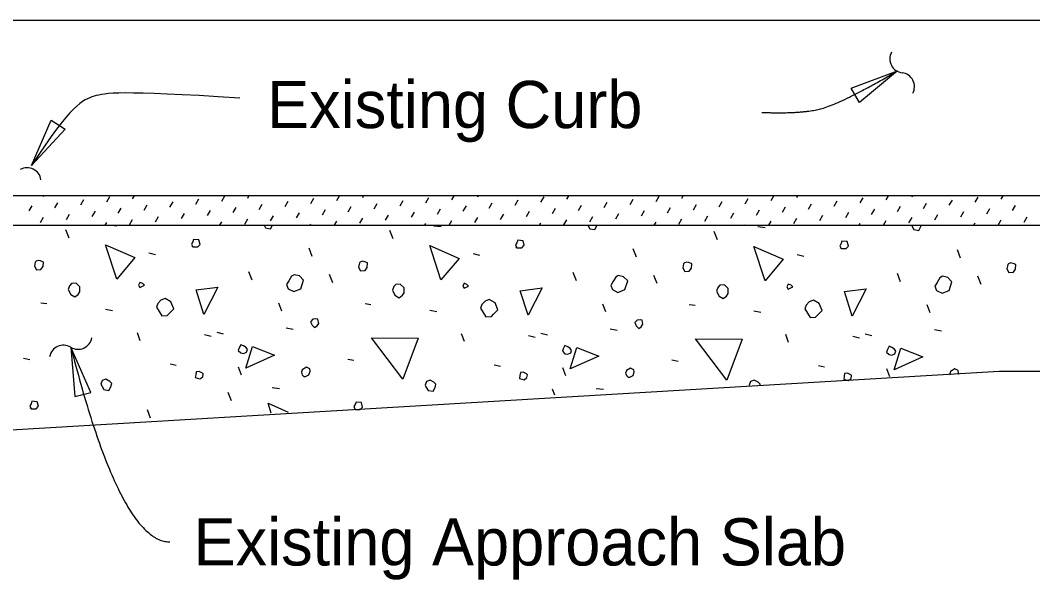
# Model space of a CAD drawing. Extents: x 21587 to 21659.1, y 56113.9 to 56155.9.
# Drawn here: x 21594.998 to 21599.323, y 56132.413 to 56134.801 of the extents above; entities that cross this region are included whole.
import ezdxf

# ---------------------------------------------------------------- set-up
doc = ezdxf.new("R2010")
doc.units = 0
for name, color, linetype in [('AdhocPoint_dp', 7, 'Continuous'), ('PlotBorder_dp', 7, 'Continuous'), ('SheetBorder_dp', 7, 'Continuous'), ('TextMisc', 7, 'Continuous')]:
    doc.layers.add(name, color=color, linetype=linetype)

msp = doc.modelspace()

# ---------------------------------------------------------------- linework, layer by layer
at = {"layer": 'AdhocPoint_dp'}
for p, q in [((21593.9596, 56134.8009), (21601.9067, 56134.8009)), ((21604.323, 56134.0511), (21593.9596, 56134.0511)), ((21593.9596, 56133.926), (21604.323, 56133.926)), ((21599.1795, 56133.301), (21594.9596, 56133.051)), ((21604.323, 56133.301), (21599.1795, 56133.301))]:
    msp.add_line(p, q, dxfattribs=at)
at = {"layer": 'PlotBorder_dp'}
for points in [[(21598.7452, 56134.5845), (21598.5825, 56134.4497), (21598.5472, 56134.5108)], [(21595.0458, 56134.1809), (21595.13, 56134.3747), (21595.1891, 56134.3361)], [(21595.2137, 56133.4055), (21595.2308, 56133.1949), (21595.2992, 56133.2123)]]:
    msp.add_lwpolyline(points, close=True, dxfattribs=at)
for centre, start, end in [((21598.7718, 56134.636), 151.5267, 263.2539), ((21598.7578, 56134.5176), 331.5267, 83.2539), ((21595.0274, 56134.1118), 7.9536, 119.6808), ((21595.2447, 56133.456), 238.4384, 350.1656), ((21595.1822, 56133.3544), 58.4384, 170.1656)]:
    msp.add_arc(centre, 0.0596, start, end, dxfattribs=at)
for points, degree in [([(21598.1653, 56134.4076), (21598.3174, 56134.4019), (21598.4885, 56134.4362), (21598.7452, 56134.5845)], 2), ([(21595.9359, 56134.4685), (21595.4144, 56134.5022), (21595.311, 56134.48), (21595.217, 56134.4435), (21595.0459, 56134.181)], 3), ([(21595.2142, 56133.4054), (21595.4254, 56132.5742), (21595.6366, 56132.5742)], 2)]:
    msp.add_open_spline(points, degree=degree, dxfattribs=at)
at = {"layer": 'TextMisc'}
for p, q in [((21595.0973, 56134.0487), (21595.0987, 56134.0511)), ((21595.3674, 56134.0258), (21595.3804, 56134.0482)), ((21595.478, 56134.0388), (21595.4852, 56134.0511)), ((21595.8588, 56134.0289), (21595.8717, 56134.0511)), ((21595.9694, 56134.0418), (21595.9748, 56134.0511)), ((21596.3501, 56134.0319), (21596.3613, 56134.0511)), ((21596.4608, 56134.0448), (21596.4644, 56134.0511)), ((21596.7309, 56134.0219), (21596.7438, 56134.0443)), ((21596.8415, 56134.0349), (21596.8509, 56134.0511)), ((21596.9521, 56134.0479), (21596.954, 56134.0511)), ((21597.2222, 56134.0249), (21597.2352, 56134.0473)), ((21597.3329, 56134.0379), (21597.3405, 56134.0511)), ((21597.4435, 56134.0509), (21597.4436, 56134.0511)), ((21597.7136, 56134.028), (21597.7266, 56134.0504)), ((21597.8242, 56134.0409), (21597.8301, 56134.0511)), ((21598.205, 56134.031), (21598.2166, 56134.0511)), ((21598.3156, 56134.044), (21598.3197, 56134.0511)), ((21598.5857, 56134.021), (21598.5987, 56134.0434)), ((21598.6963, 56134.034), (21598.7062, 56134.0511)), ((21598.807, 56134.047), (21598.8094, 56134.0511)), ((21599.0771, 56134.0241), (21599.09, 56134.0465)), ((21599.1877, 56134.037), (21599.1958, 56134.0511)), ((21599.2983, 56134.05), (21599.299, 56134.0511)), ((21595.0355, 56133.9869), (21595.0485, 56134.0093)), ((21595.1462, 56133.9999), (21595.1591, 56134.0223)), ((21595.2568, 56134.0129), (21595.2697, 56134.0353)), ((21595.4163, 56133.977), (21595.4292, 56133.9994)), ((21595.5269, 56133.99), (21595.5398, 56134.0124)), ((21595.6375, 56134.0029), (21595.6505, 56134.0253)), ((21595.7481, 56134.0159), (21595.7611, 56134.0383)), ((21595.9076, 56133.98), (21595.9206, 56134.0024)), ((21596.0182, 56133.993), (21596.0312, 56134.0154)), ((21596.1289, 56134.0059), (21596.1418, 56134.0283)), ((21596.2395, 56134.0189), (21596.2525, 56134.0413)), ((21596.399, 56133.983), (21596.4119, 56134.0054)), ((21596.5096, 56133.996), (21596.5226, 56134.0184)), ((21596.6202, 56134.009), (21596.6332, 56134.0314)), ((21596.8903, 56133.9861), (21596.9033, 56134.0084)), ((21597.001, 56133.999), (21597.0139, 56134.0214)), ((21597.1116, 56134.012), (21597.1246, 56134.0344)), ((21597.3817, 56133.9891), (21597.3947, 56134.0115)), ((21597.4923, 56134.002), (21597.5053, 56134.0244)), ((21597.603, 56134.015), (21597.6159, 56134.0374)), ((21597.7624, 56133.9791), (21597.7754, 56134.0015)), ((21597.8731, 56133.9921), (21597.886, 56134.0145)), ((21597.9837, 56134.0051), (21597.9967, 56134.0275)), ((21598.0943, 56134.018), (21598.1073, 56134.0404)), ((21598.2538, 56133.9822), (21598.2668, 56134.0045)), ((21598.3644, 56133.9951), (21598.3774, 56134.0175)), ((21598.4751, 56134.0081), (21598.488, 56134.0305)), ((21598.7452, 56133.9852), (21598.7581, 56134.0076)), ((21598.8558, 56133.9981), (21598.8688, 56134.0205)), ((21598.9664, 56134.0111), (21598.9794, 56134.0335)), ((21599.2365, 56133.9882), (21599.2495, 56134.0106)), ((21595.0844, 56133.9381), (21595.0973, 56133.9605)), ((21595.195, 56133.9511), (21595.2079, 56133.9735)), ((21595.3056, 56133.964), (21595.3186, 56133.9864)), ((21595.5757, 56133.9411), (21595.5887, 56133.9635)), ((21595.6864, 56133.9541), (21595.6993, 56133.9765)), ((21595.797, 56133.9671), (21595.8099, 56133.9894)), ((21596.0671, 56133.9441), (21596.08, 56133.9665)), ((21596.1777, 56133.9571), (21596.1907, 56133.9795)), ((21596.2883, 56133.9701), (21596.3013, 56133.9925)), ((21596.4478, 56133.9342), (21596.4608, 56133.9566)), ((21596.5584, 56133.9472), (21596.5714, 56133.9696)), ((21596.6691, 56133.9601), (21596.682, 56133.9825)), ((21596.7797, 56133.9731), (21596.7927, 56133.9955)), ((21596.9392, 56133.9372), (21596.9521, 56133.9596)), ((21597.0498, 56133.9502), (21597.0628, 56133.9726)), ((21597.1604, 56133.9631), (21597.1734, 56133.9855)), ((21597.2711, 56133.9761), (21597.284, 56133.9985)), ((21597.4305, 56133.9402), (21597.4435, 56133.9626)), ((21597.5412, 56133.9532), (21597.5541, 56133.9756)), ((21597.6518, 56133.9662), (21597.6648, 56133.9886)), ((21597.9219, 56133.9433), (21597.9349, 56133.9657)), ((21598.0325, 56133.9562), (21598.0455, 56133.9786)), ((21598.1432, 56133.9692), (21598.1561, 56133.9916)), ((21598.4133, 56133.9463), (21598.4262, 56133.9687)), ((21598.5239, 56133.9592), (21598.5369, 56133.9816)), ((21598.6345, 56133.9722), (21598.6475, 56133.9946)), ((21598.794, 56133.9363), (21598.807, 56133.9587)), ((21598.9046, 56133.9493), (21598.9176, 56133.9717)), ((21599.0153, 56133.9623), (21599.0282, 56133.9847)), ((21599.1259, 56133.9752), (21599.1389, 56133.9976)), ((21599.2854, 56133.9394), (21599.2983, 56133.9617)), ((21595.3607, 56133.926), (21595.3674, 56133.9376)), ((21595.3891, 56133.926), (21595.411, 56133.9236)), ((21595.4651, 56133.9282), (21595.478, 56133.9506)), ((21595.7472, 56133.926), (21595.7481, 56133.9276)), ((21595.8503, 56133.926), (21595.8588, 56133.9406)), ((21595.9565, 56133.9312), (21595.9694, 56133.9536)), ((21596.2368, 56133.926), (21596.2395, 56133.9307)), ((21596.34, 56133.926), (21596.3501, 56133.9436)), ((21596.7264, 56133.926), (21596.7309, 56133.9337)), ((21596.7639, 56133.9236), (21596.7957, 56133.9201)), ((21596.8296, 56133.926), (21596.8415, 56133.9466)), ((21597.2161, 56133.926), (21597.2222, 56133.9367)), ((21597.3199, 56133.9273), (21597.3329, 56133.9497)), ((21597.6025, 56133.926), (21597.603, 56133.9268)), ((21597.7057, 56133.926), (21597.7136, 56133.9397)), ((21597.8113, 56133.9303), (21597.8242, 56133.9527)), ((21598.0922, 56133.926), (21598.0943, 56133.9298)), ((21598.1485, 56133.9201), (21598.1804, 56133.9165)), ((21598.1953, 56133.926), (21598.205, 56133.9427)), ((21598.3026, 56133.9333), (21598.3156, 56133.9557)), ((21598.5818, 56133.926), (21598.5857, 56133.9328)), ((21598.6849, 56133.926), (21598.6963, 56133.9458)), ((21599.0714, 56133.926), (21599.0771, 56133.9358)), ((21599.1747, 56133.9264), (21599.1877, 56133.9488)), ((21595.2066, 56133.8712), (21595.1924, 56133.9065)), ((21596.5913, 56133.8676), (21596.5771, 56133.903)), ((21597.9759, 56133.8641), (21597.9618, 56133.8995)), ((21596.2454, 56133.7928), (21596.2313, 56133.8281)), ((21595.5471, 56133.8087), (21595.5754, 56133.8016)), ((21596.9318, 56133.8051), (21596.9601, 56133.7981)), ((21597.6301, 56133.7892), (21597.6159, 56133.8246)), ((21598.3165, 56133.8016), (21598.3448, 56133.7945)), ((21599.0148, 56133.7857), (21599.0006, 56133.8211)), ((21595.9891, 56133.692), (21595.9749, 56133.7274)), ((21596.3332, 56133.6803), (21596.319, 56133.7156)), ((21597.3737, 56133.6885), (21597.3596, 56133.7238)), ((21597.7178, 56133.6767), (21597.7037, 56133.7121)), ((21598.7584, 56133.6849), (21598.7443, 56133.7203)), ((21599.1025, 56133.6732), (21599.0884, 56133.7085)), ((21595.0864, 56133.5954), (21595.1111, 56133.5919)), ((21595.3621, 56133.5671), (21595.3922, 56133.5618)), ((21596.1146, 56133.5594), (21596.1022, 56133.593)), ((21596.471, 56133.5919), (21596.4958, 56133.5883)), ((21597.4993, 56133.5559), (21597.4869, 56133.5895)), ((21597.8557, 56133.5883), (21597.8805, 56133.5848)), ((21598.8839, 56133.5524), (21598.8716, 56133.5859)), ((21596.7468, 56133.5636), (21596.7769, 56133.5583)), ((21598.1315, 56133.5601), (21598.1615, 56133.5547)), ((21596.1334, 56133.4876), (21596.1635, 56133.4823)), ((21597.5181, 56133.484), (21597.5481, 56133.4787)), ((21598.9028, 56133.4805), (21598.9328, 56133.4752)), ((21595.5106, 56133.4328), (21595.4983, 56133.4664)), ((21595.7846, 56133.4593), (21595.8129, 56133.4522)), ((21595.837, 56133.4693), (21595.8653, 56133.4622)), ((21596.8953, 56133.4292), (21596.8829, 56133.4628)), ((21597.1693, 56133.4558), (21597.1976, 56133.4487)), ((21597.2217, 56133.4657), (21597.25, 56133.4587)), ((21598.28, 56133.4257), (21598.2676, 56133.4593)), ((21598.554, 56133.4522), (21598.5823, 56133.4451)), ((21598.6064, 56133.4622), (21598.6347, 56133.4551)), ((21595.0121, 56133.3585), (21595.0386, 56133.3532)), ((21596.3968, 56133.355), (21596.4233, 56133.3497)), ((21597.7815, 56133.3515), (21597.808, 56133.3462)), ((21595.6379, 56133.3338), (21595.6644, 56133.3285)), ((21595.9431, 56133.2867), (21595.9307, 56133.3203)), ((21597.0226, 56133.3302), (21597.0491, 56133.3249)), ((21597.3278, 56133.2831), (21597.3154, 56133.3167)), ((21598.4073, 56133.3267), (21598.4338, 56133.3214)), ((21598.7125, 56133.2796), (21598.7001, 56133.3132)), ((21596.0733, 56133.233), (21596.1051, 56133.2295)), ((21597.2818, 56133.2001), (21597.2712, 56133.2267)), ((21597.458, 56133.2295), (21597.4898, 56133.2259)), ((21595.9007, 56133.1771), (21595.8865, 56133.2124)), ((21595.5548, 56133.1022), (21595.5407, 56133.1376))]:
    msp.add_line(p, q, dxfattribs=at)
for points in [[(21596.0394, 56133.926), (21596.0456, 56133.9147), (21596.0669, 56133.9112), (21596.0751, 56133.926)], [(21597.4221, 56133.926), (21597.4303, 56133.9112), (21597.4515, 56133.9077), (21597.4604, 56133.9236), (21597.461, 56133.926)], [(21598.8049, 56133.926), (21598.8062, 56133.9236)], [(21598.8062, 56133.9236), (21598.815, 56133.9077), (21598.8362, 56133.9041), (21598.845, 56133.9201), (21598.8465, 56133.926)], [(21595.4099, 56133.6962), (21595.3621, 56133.8429), (21595.4877, 56133.7881), (21595.4099, 56133.6962)], [(21595.7345, 56133.8334), (21595.7557, 56133.8334), (21595.7663, 56133.844), (21595.761, 56133.8635), (21595.738, 56133.8653), (21595.7345, 56133.8546), (21595.7292, 56133.8458), (21595.7345, 56133.8334), (21595.731, 56133.837)], [(21596.7945, 56133.6926), (21596.7468, 56133.8394), (21596.8723, 56133.7846), (21596.7945, 56133.6926)], [(21597.1192, 56133.8299), (21597.1404, 56133.8299), (21597.151, 56133.8405), (21597.1457, 56133.8599), (21597.1227, 56133.8617), (21597.1192, 56133.8511), (21597.1139, 56133.8423), (21597.1192, 56133.8299), (21597.1157, 56133.8334)], [(21598.1792, 56133.6891), (21598.1315, 56133.8358), (21598.257, 56133.781), (21598.1792, 56133.6891)], [(21598.5039, 56133.8264), (21598.5251, 56133.8264), (21598.5357, 56133.837), (21598.5304, 56133.8564), (21598.5074, 56133.8582), (21598.5039, 56133.8476), (21598.4986, 56133.8387), (21598.5039, 56133.8264), (21598.5003, 56133.8299)], [(21595.0581, 56133.751), (21595.0669, 56133.7351), (21595.0864, 56133.7368), (21595.0952, 56133.7492), (21595.097, 56133.7686), (21595.0846, 56133.774), (21595.0758, 56133.7757), (21595.0652, 56133.7722), (21595.0616, 56133.7686), (21595.0581, 56133.751)], [(21596.4428, 56133.7474), (21596.4516, 56133.7315), (21596.471, 56133.7333), (21596.4799, 56133.7457), (21596.4817, 56133.7651), (21596.4693, 56133.7704), (21596.4604, 56133.7722), (21596.4498, 56133.7686), (21596.4463, 56133.7651), (21596.4428, 56133.7474)], [(21597.8274, 56133.7439), (21597.8363, 56133.728), (21597.8557, 56133.7298), (21597.8646, 56133.7421), (21597.8663, 56133.7616), (21597.854, 56133.7669), (21597.8451, 56133.7686), (21597.8345, 56133.7651), (21597.831, 56133.7616), (21597.8274, 56133.7439)], [(21599.2121, 56133.7404), (21599.221, 56133.7245), (21599.2404, 56133.7262), (21599.2492, 56133.7386), (21599.251, 56133.758), (21599.2386, 56133.7633), (21599.2298, 56133.7651), (21599.2192, 56133.7616), (21599.2156, 56133.758), (21599.2121, 56133.7404)], [(21596.1429, 56133.6549), (21596.1658, 56133.6425), (21596.1959, 56133.6549), (21596.2083, 56133.692), (21596.1906, 56133.7097), (21596.1676, 56133.715), (21596.157, 56133.7079), (21596.1446, 56133.6885), (21596.1358, 56133.6726), (21596.1429, 56133.6549)], [(21597.5275, 56133.6514), (21597.5505, 56133.639), (21597.5806, 56133.6514), (21597.593, 56133.6885), (21597.5753, 56133.7062), (21597.5523, 56133.7115), (21597.5417, 56133.7044), (21597.5293, 56133.6849), (21597.5205, 56133.669), (21597.5275, 56133.6514)], [(21598.9122, 56133.6478), (21598.9352, 56133.6354), (21598.9653, 56133.6478), (21598.9776, 56133.6849), (21598.9599, 56133.7026), (21598.937, 56133.7079), (21598.9264, 56133.7008), (21598.914, 56133.6814), (21598.9051, 56133.6655), (21598.9122, 56133.6478)], [(21595.203, 56133.652), (21595.2136, 56133.6308), (21595.2313, 56133.6202), (21595.2455, 56133.6308), (21595.2525, 56133.6414), (21595.2525, 56133.6626), (21595.2366, 56133.6785), (21595.2172, 56133.6767), (21595.2083, 56133.6679), (21595.203, 56133.652)], [(21595.5089, 56133.6608), (21595.5283, 56133.6697), (21595.5212, 56133.6767), (21595.5089, 56133.682), (21595.5036, 56133.6697), (21595.5089, 56133.6608)], [(21595.7822, 56133.5453), (21595.7487, 56133.6496), (21595.8423, 56133.662), (21595.7822, 56133.5453)], [(21596.5877, 56133.6484), (21596.5983, 56133.6272), (21596.616, 56133.6166), (21596.6301, 56133.6272), (21596.6372, 56133.6378), (21596.6372, 56133.659), (21596.6213, 56133.675), (21596.6019, 56133.6732), (21596.593, 56133.6644), (21596.5877, 56133.6484)], [(21596.8935, 56133.6573), (21596.913, 56133.6661), (21596.9059, 56133.6732), (21596.8935, 56133.6785), (21596.8882, 56133.6661), (21596.8935, 56133.6573)], [(21597.1669, 56133.5417), (21597.1333, 56133.646), (21597.227, 56133.6584), (21597.1669, 56133.5417)], [(21597.9724, 56133.6449), (21597.983, 56133.6237), (21598.0007, 56133.6131), (21598.0148, 56133.6237), (21598.0219, 56133.6343), (21598.0219, 56133.6555), (21598.006, 56133.6714), (21597.9865, 56133.6697), (21597.9777, 56133.6608), (21597.9724, 56133.6449)], [(21598.2782, 56133.6537), (21598.2977, 56133.6626), (21598.2906, 56133.6697), (21598.2782, 56133.675), (21598.2729, 56133.6626), (21598.2782, 56133.6537)], [(21598.5516, 56133.5382), (21598.518, 56133.6425), (21598.6117, 56133.6549), (21598.5516, 56133.5382)], [(21595.5796, 56133.576), (21595.6026, 56133.5388), (21595.6255, 56133.5406), (21595.6344, 56133.5494), (21595.6538, 56133.5689), (21595.6414, 56133.5989), (21595.6167, 56133.6131), (21595.599, 56133.606), (21595.5849, 56133.5919), (21595.5796, 56133.576)], [(21596.9643, 56133.5724), (21596.9872, 56133.5353), (21597.0102, 56133.5371), (21597.0191, 56133.5459), (21597.0385, 56133.5654), (21597.0261, 56133.5954), (21597.0014, 56133.6096), (21596.9837, 56133.6025), (21596.9696, 56133.5883), (21596.9643, 56133.5724)], [(21598.3489, 56133.5689), (21598.3719, 56133.5318), (21598.3949, 56133.5335), (21598.4037, 56133.5424), (21598.4232, 56133.5618), (21598.4108, 56133.5919), (21598.3861, 56133.606), (21598.3684, 56133.5989), (21598.3542, 56133.5848), (21598.3489, 56133.5689)], [(21596.2448, 56133.4999), (21596.2554, 56133.4893), (21596.266, 56133.4964), (21596.2731, 56133.507), (21596.2695, 56133.5247), (21596.2607, 56133.5265), (21596.2483, 56133.5247), (21596.2377, 56133.5141), (21596.2448, 56133.4999)], [(21597.6294, 56133.4964), (21597.6401, 56133.4858), (21597.6507, 56133.4929), (21597.6577, 56133.5035), (21597.6542, 56133.5212), (21597.6454, 56133.5229), (21597.633, 56133.5212), (21597.6224, 56133.5106), (21597.6294, 56133.4964)], [(21596.6319, 56133.2684), (21596.4976, 56133.4451), (21596.6973, 56133.4434), (21596.6319, 56133.2684)], [(21598.0166, 56133.2648), (21597.8822, 56133.4416), (21598.082, 56133.4398), (21598.0166, 56133.2648)], [(21595.9396, 56133.3809), (21595.9519, 56133.3791), (21595.9643, 56133.3844), (21595.9679, 56133.395), (21595.9626, 56133.4039), (21595.9519, 56133.4109), (21595.9396, 56133.4162), (21595.9325, 56133.4021), (21595.929, 56133.3915), (21595.9396, 56133.3809)], [(21595.9619, 56133.3161), (21595.9902, 56133.408), (21596.0839, 56133.3709), (21595.9619, 56133.3161)], [(21597.3242, 56133.3773), (21597.3366, 56133.3756), (21597.349, 56133.3809), (21597.3525, 56133.3915), (21597.3472, 56133.4003), (21597.3366, 56133.4074), (21597.3242, 56133.4127), (21597.3172, 56133.3986), (21597.3136, 56133.388), (21597.3242, 56133.3773)], [(21597.3466, 56133.3126), (21597.3749, 56133.4045), (21597.4686, 56133.3674), (21597.3466, 56133.3126)], [(21598.7089, 56133.3738), (21598.7213, 56133.372), (21598.7337, 56133.3773), (21598.7372, 56133.388), (21598.7319, 56133.3968), (21598.7213, 56133.4039), (21598.7089, 56133.4092), (21598.7019, 56133.395), (21598.6983, 56133.3844), (21598.7089, 56133.3738)], [(21598.7313, 56133.309), (21598.7596, 56133.401), (21598.8533, 56133.3638), (21598.7313, 56133.309)], [(21596.2094, 56133.2807), (21596.2165, 56133.2807), (21596.2306, 56133.2878), (21596.2359, 56133.3037), (21596.2342, 56133.3126), (21596.22, 56133.3196), (21596.2023, 56133.309), (21596.1988, 56133.2984), (21596.2023, 56133.2878), (21596.2094, 56133.2807)], [(21597.5941, 56133.2772), (21597.6012, 56133.2772), (21597.6153, 56133.2843), (21597.6206, 56133.3002), (21597.6188, 56133.309), (21597.6047, 56133.3161), (21597.587, 56133.3055), (21597.5835, 56133.2949), (21597.587, 56133.2843), (21597.5941, 56133.2772)], [(21599.003, 56133.2899), (21599.0053, 56133.2967), (21599.0035, 56133.3055), (21598.9894, 56133.3126), (21598.9717, 56133.302), (21598.9682, 56133.2914), (21598.9693, 56133.2878)], [(21595.3462, 56133.2401), (21595.3551, 56133.2242), (21595.3763, 56133.2206), (21595.3851, 56133.2366), (21595.3887, 56133.2507), (21595.3798, 56133.2595), (21595.3639, 56133.2684), (21595.348, 56133.2631), (21595.3427, 56133.2472), (21595.3462, 56133.2401)], [(21595.7457, 56133.2754), (21595.7652, 56133.2701), (21595.7776, 56133.279), (21595.7793, 56133.2914), (21595.7758, 56133.2949), (21595.7617, 56133.302), (21595.7493, 56133.3002), (21595.7475, 56133.2878), (21595.7457, 56133.2754)], [(21596.7309, 56133.2366), (21596.7397, 56133.2206), (21596.761, 56133.2171), (21596.7698, 56133.233), (21596.7733, 56133.2472), (21596.7645, 56133.256), (21596.7486, 56133.2648), (21596.7327, 56133.2595), (21596.7274, 56133.2436), (21596.7309, 56133.2366)], [(21597.1304, 56133.2719), (21597.1499, 56133.2666), (21597.1622, 56133.2754), (21597.164, 56133.2878), (21597.1605, 56133.2914), (21597.1463, 56133.2984), (21597.134, 56133.2967), (21597.1322, 56133.2843), (21597.1304, 56133.2719)], [(21598.1564, 56133.2405), (21598.158, 56133.2471), (21598.1492, 56133.256), (21598.1333, 56133.2648), (21598.1174, 56133.2595), (21598.112, 56133.2436), (21598.1149, 56133.2379)], [(21598.5151, 56133.2684), (21598.5345, 56133.2631), (21598.5469, 56133.2719), (21598.5487, 56133.2843), (21598.5452, 56133.2878), (21598.531, 56133.2949), (21598.5186, 56133.2931), (21598.5169, 56133.2807), (21598.5151, 56133.2684)], [(21595.0439, 56133.1429), (21595.0652, 56133.1429), (21595.0758, 56133.1535), (21595.0705, 56133.1729), (21595.0475, 56133.1747), (21595.0439, 56133.1641), (21595.0386, 56133.1552), (21595.0439, 56133.1429), (21595.0404, 56133.1464)], [(21596.07, 56133.1238), (21596.0562, 56133.1659), (21596.1425, 56133.1283)], [(21596.4286, 56133.1393), (21596.4498, 56133.1393), (21596.4604, 56133.1499), (21596.4551, 56133.1694), (21596.4322, 56133.1711), (21596.4286, 56133.1605), (21596.4233, 56133.1517), (21596.4286, 56133.1393), (21596.4251, 56133.1429)]]:
    msp.add_lwpolyline(points, dxfattribs=at)

# ---------------------------------------------------------------- texts
at = {"layer": 'SheetBorder_dp'}
for s, p in [('Existing Curb', (21596.0521, 56134.3406)), ('Existing Approach Slab', (21595.7377, 56132.4736))]:
    msp.add_text(s, height=0.2016, dxfattribs=at).set_placement(p)

doc.saveas('drawing.dxf')
